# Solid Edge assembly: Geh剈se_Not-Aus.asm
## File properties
Author: Ferdi HM
Template: Din Metric Assembly.asm
Last saved by: Ferdi
Revision: 11
Application: Solid Edge
Username: Ferdi HM
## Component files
Gehaeuse_Not-Aus.par
Gehaeuse_Unterteil.par
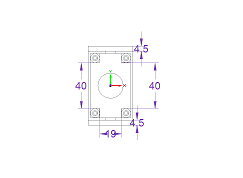
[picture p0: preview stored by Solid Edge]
